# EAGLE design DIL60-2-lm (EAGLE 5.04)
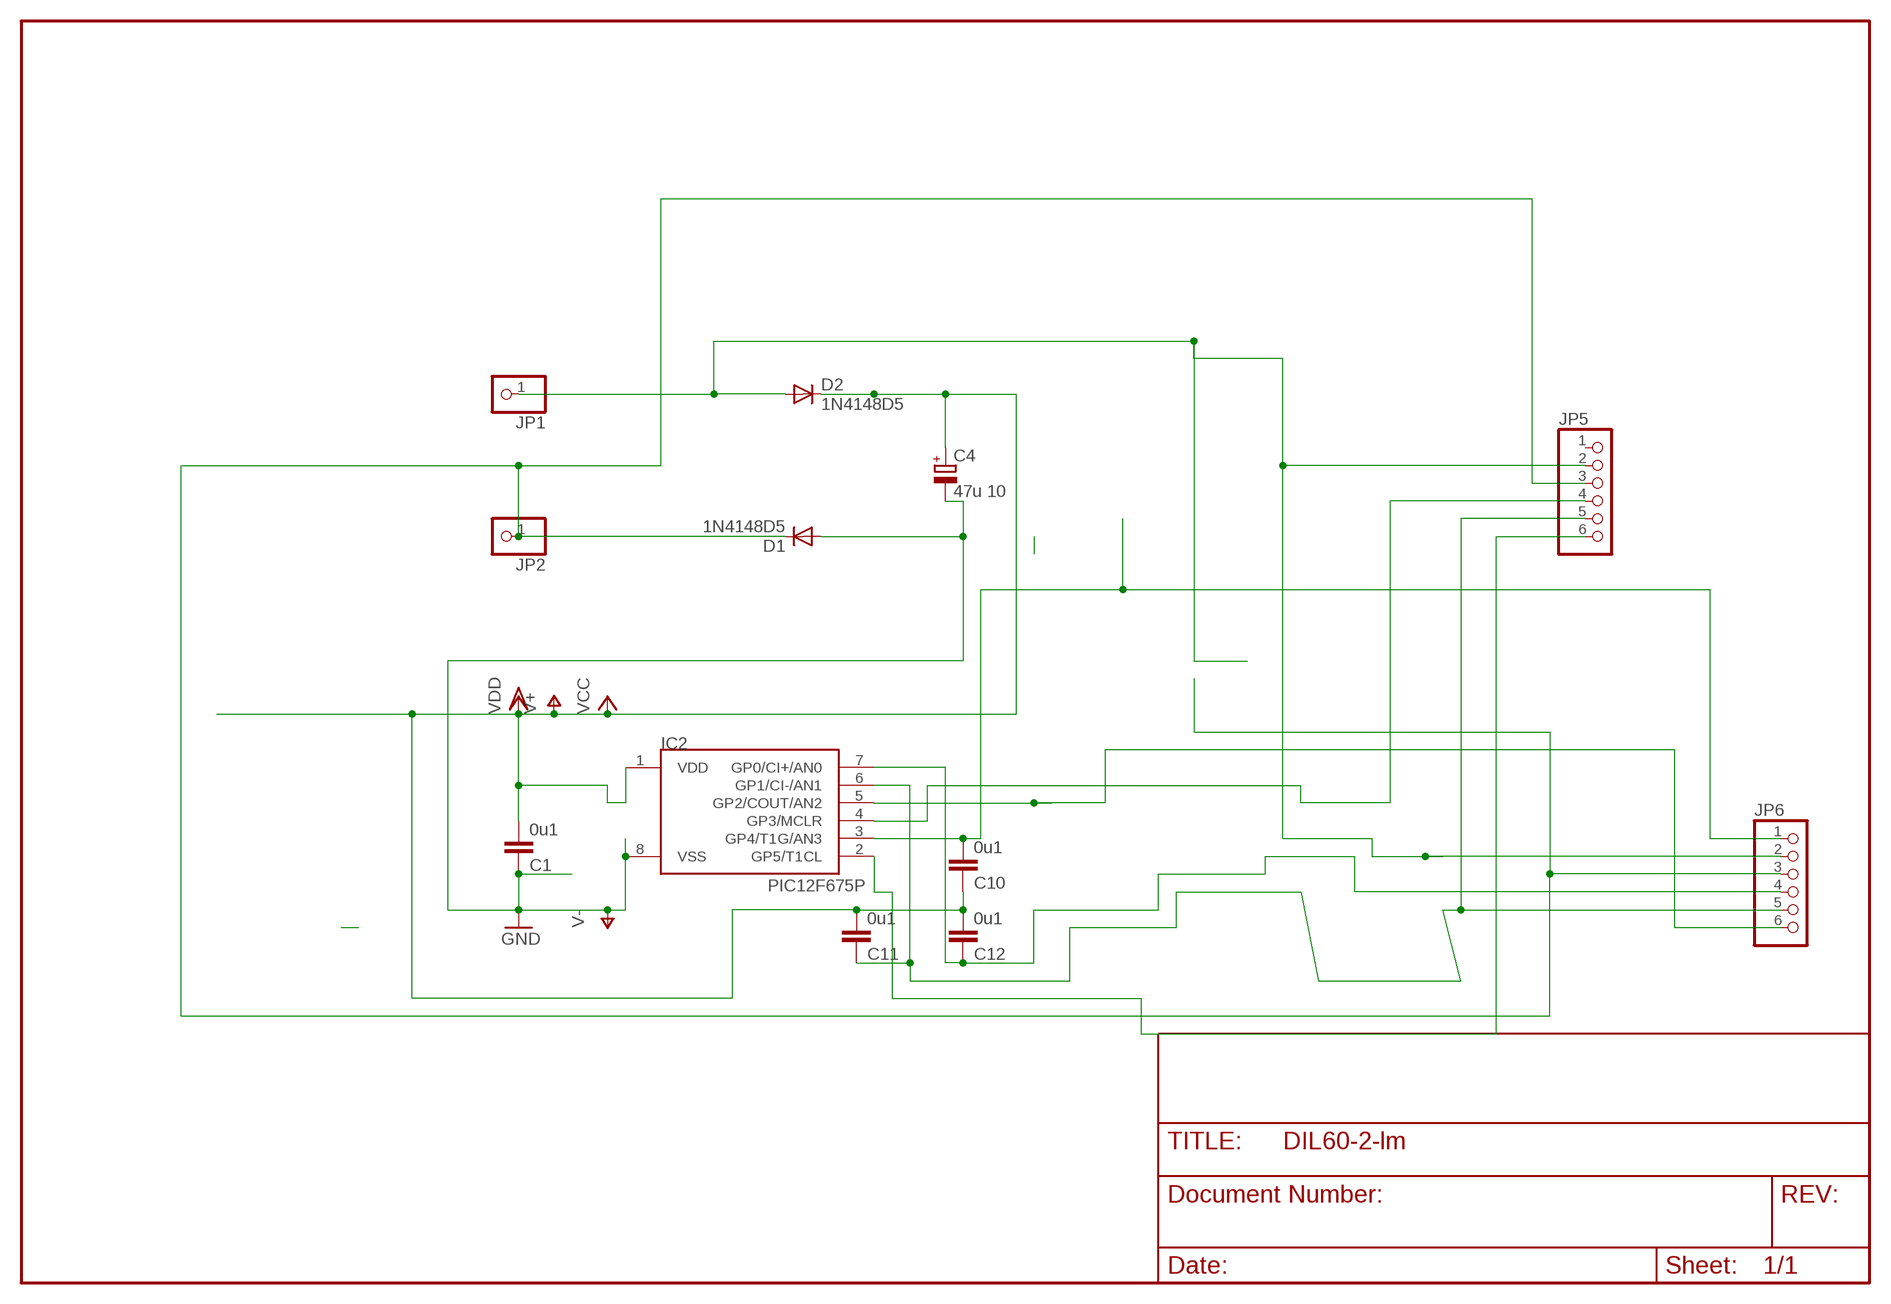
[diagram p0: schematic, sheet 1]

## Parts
C1  0u1  C-EUC1206  [C1206]
C4  47u 10  CPOL-EUE2.5-6  [E2,5-6]
C10  0u1  C-EUC1206  [C1206]
C11  0u1  C-EUC1206  [C1206]
C12  0u1  C-EUC1206  [C1206]
D1  1N4148D5  [D-5]
D2  1N4148D5  [D-5]
IC2  PIC12F675P  [DIL8]
JP1  PINHD-1X1  [1X01]
JP2  PINHD-1X1  [1X01]
JP5  PINHD-1X6  [1X06]
JP6  PINHD-1X6  [1X06]

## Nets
GND: C1.1 C4.- D1.A IC2.8(VSS) ; supply symbol labelled V-
N$2: IC2.5(GP2/COUT/AN2) JP6.6
N$3: IC2.4(GP3/MCLR) JP5.4
N$4: C10.2 IC2.3(GP4/T1G/AN3) JP6.1
N$7: D1.C JP2.1 JP5.3 JP6.3
N$8: IC2.2(GP5/T1CL) JP5.6
N$13: C12.1 IC2.7(GP0/CI+/AN0) JP6.4
N$15: C11.1 IC2.6(GP1/CI-/AN1) JP5.5 JP6.5
V+: C1.2 C4.+ C10.1 C11.2 C12.2 D2.C IC2.1(VDD) ; supply symbol labelled VDD, VCC
VDD: D2.A JP1.1 JP5.2 JP6.2
Unconnected: JP5.1

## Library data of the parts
C1 C10-C12 = rcl:C-EU: CAPACITOR, European symbol
C4 = rcl:CPOL-EU: POLARIZED CAPACITOR, European symbol
D1 D2 = diode:1N4148: DIODE
IC2 = microchip-3:PIC12F6*: uPC nW 1k Program Flash memory 2x Timer Comparator 10b A/D converter/ 4xIN
JP1 JP2 = pinhead:PINHD-1X1: PIN HEADER
JP5 JP6 = pinhead:PINHD-1X6: PIN HEADER

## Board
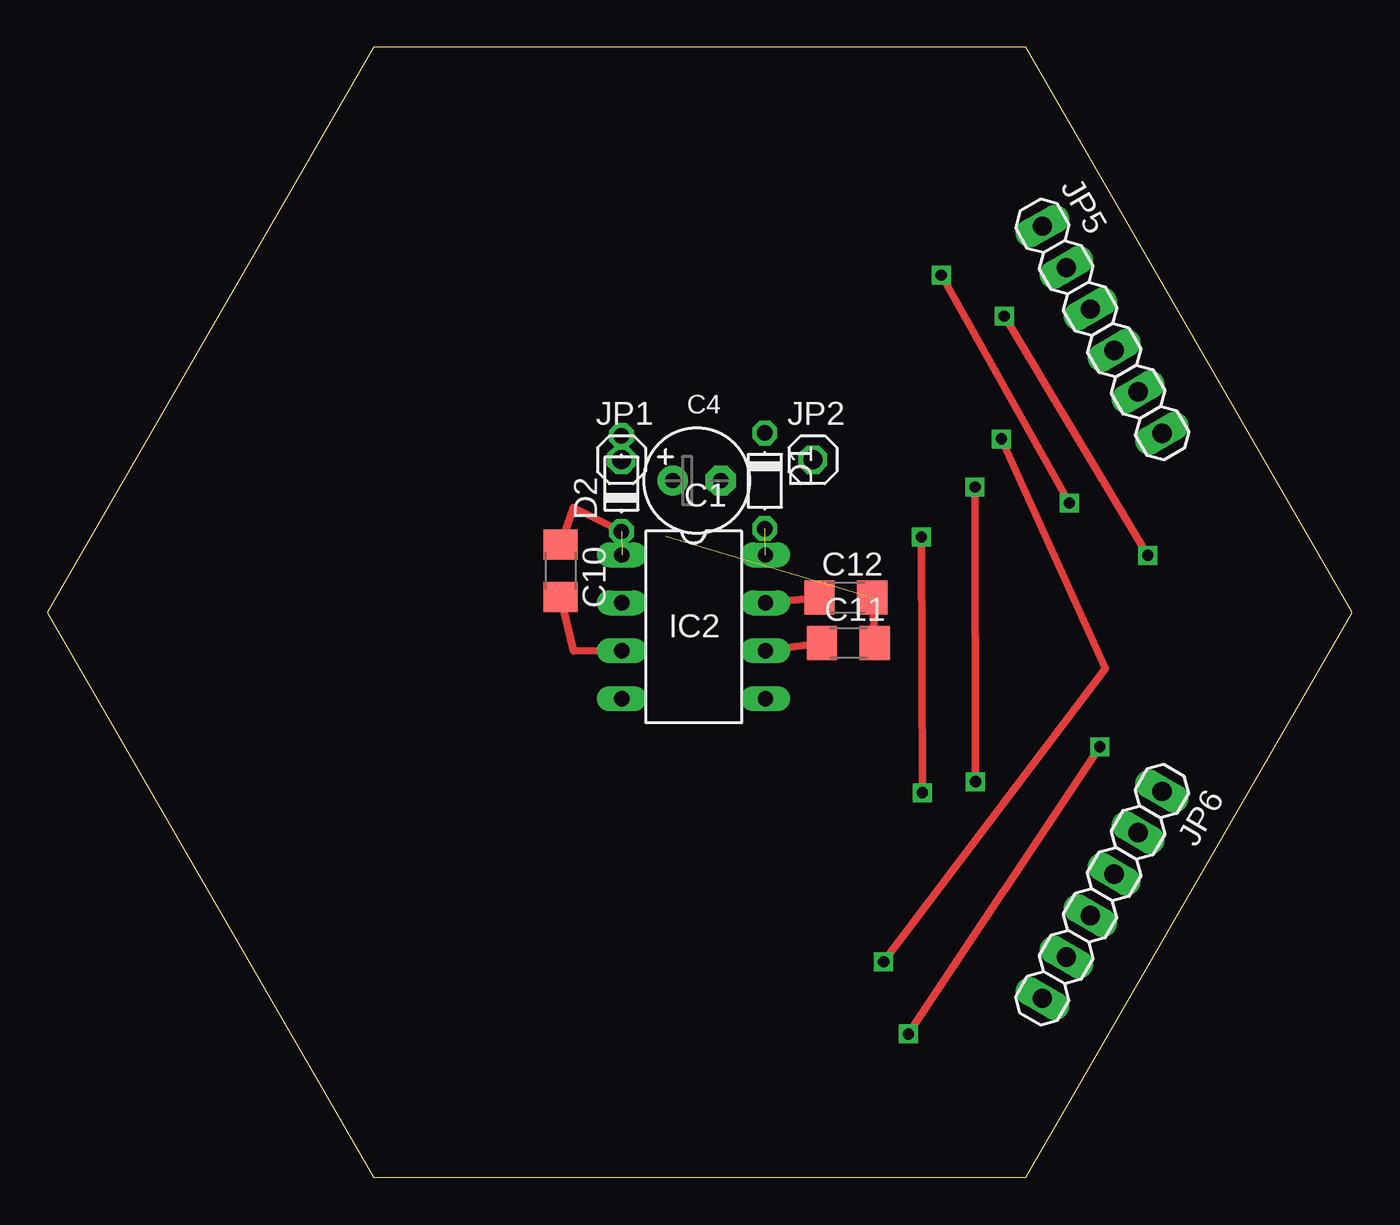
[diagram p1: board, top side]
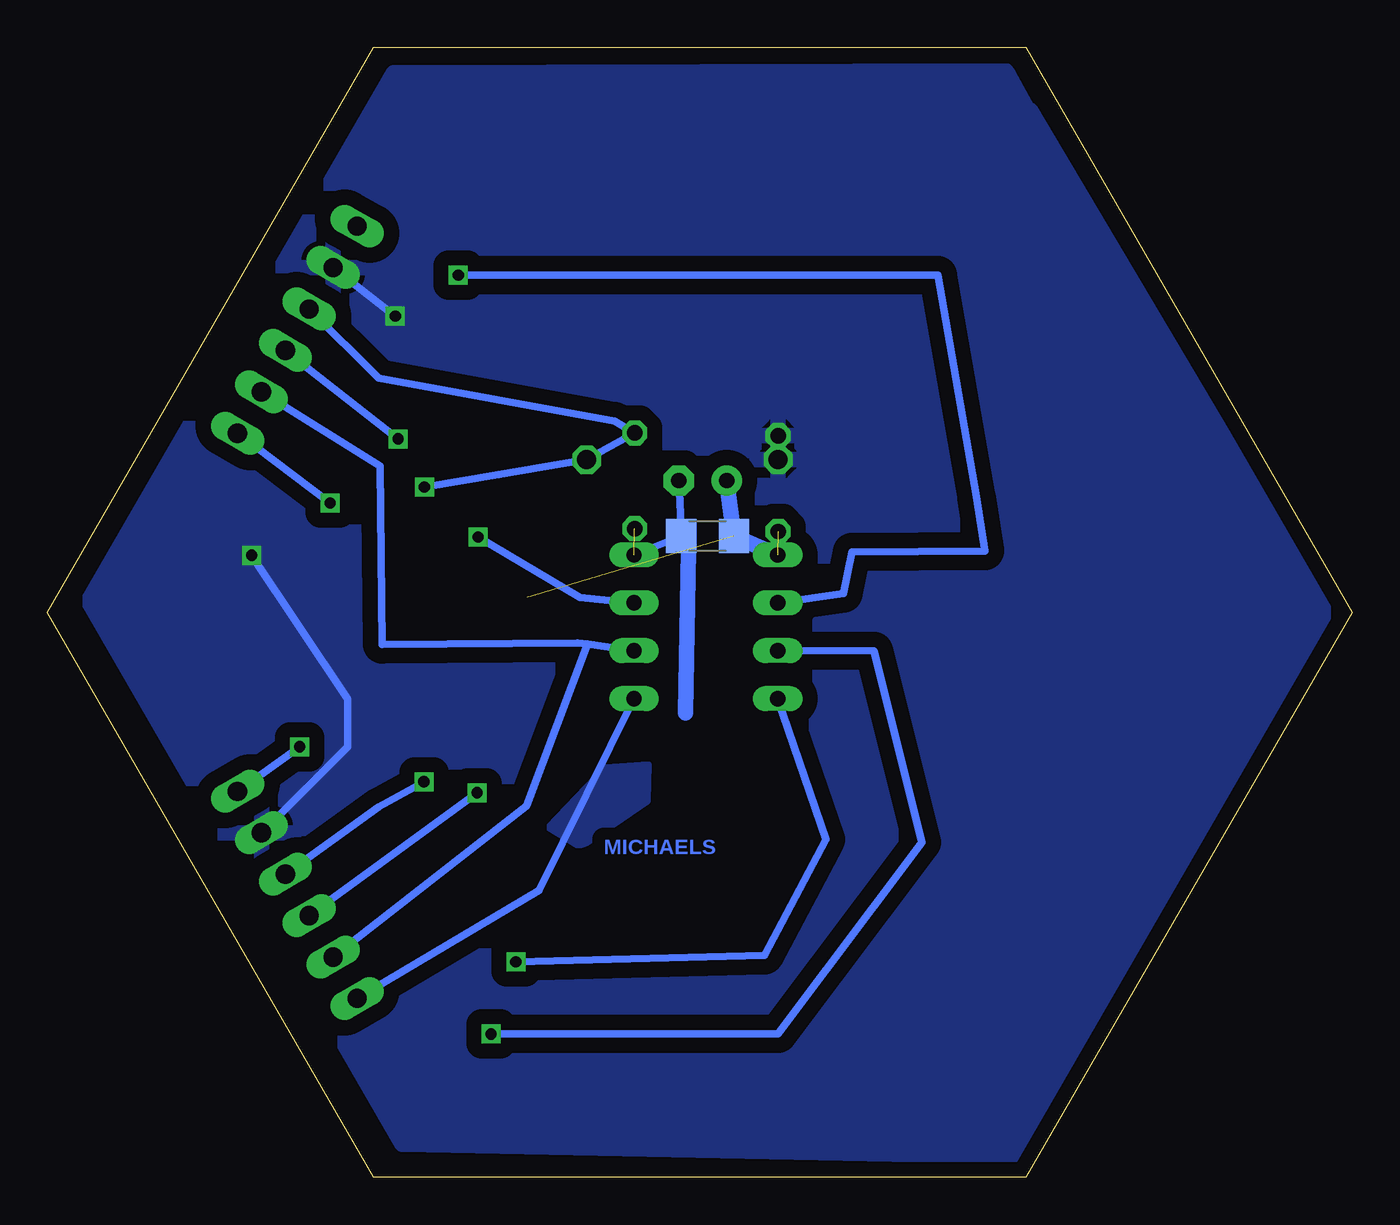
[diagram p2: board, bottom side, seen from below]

Size 69.28 x 60 mm. Coordinates in mm from the lower left corner, seen from the top.
Outline: 17.32,0 51.96,0 69.28,30 51.96,60 17.32,60 0,30 17.32,0
Copper layers (1*16): Top 0.035mm / dielectric 1.5mm / Bottom 0.035mm
Design rules "default *": minimum track width 10mil, minimum drill 24mil, track to track 8mil, track to pad 8mil, pad to pad 8mil, via to via 8mil, smd to smd 8mil, copper to edge 10mil, drill to drill 8mil, minimum pad ring 10mil, minimum via ring 8mil, stop-mask expansion 4mil, vias tented up to drill 0mil, thermal gap 10mil

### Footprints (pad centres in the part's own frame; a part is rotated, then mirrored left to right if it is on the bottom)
C1206 = smd 1.6 x 1.8: 1 -1.4,0; 2 1.4,0
E2,5-6 = drill 0.813 pad 1.6 round: + -1.27,0 | drill 0.813 pad 1.6 octagon: - 1.27,0
D-5 = drill 0.813 octagon: A 2.54,0; C -2.54,0
DIL8 = drill 0.813 long: 1 -3.81,-3.81; 2 -1.27,-3.81; 3 1.27,-3.81; 4 3.81,-3.81; 5 3.81,3.81; 6 1.27,3.81; 7 -1.27,3.81; 8 -3.81,3.81
1X01 = drill 1.016 octagon: 1 0,0
1X06 = drill 1.016 long: 1 -6.35,0; 2 -3.81,0; 3 -1.27,0; 4 1.27,0; 5 3.81,0; 6 6.35,0

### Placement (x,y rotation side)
C1  34.22,34.05 0 bottom
C4  34.48,36.99 0 top
C10  27.25,32.2 270 top
C11  42.53,28.38 0 top
C12  42.39,30.78 0 top
D1  38.09,36.98 270 top
D2  30.48,36.83 90 top
IC2  34.32,29.23 270 top
JP1  30.48,38.1 0 top
JP2  40.64,38.1 0 top
JP5  56,45 300 top
JP6  56,15 240 top

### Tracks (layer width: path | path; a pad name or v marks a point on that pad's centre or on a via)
GND  (1 unrouted)
  Bottom 0.406: C1.1 IC2.8 | 35.25,33.3 C1.1 | C1.1 C4.-
  Bottom 0.813: 35.4,24.65 35.25,33.3
N$2
  Bottom 0.406: JP6.6 43.18,15.24 IC2.5
  pour Bottom (isolate 0.61): 40.64,17.78 37.43,19.99 37.38,21.89 39.63,21.74 42.63,18.59 41.08,17.64
N$3  (via drill 0.6)
  Top 0.406: v50.65,39.2 56.18,27.02 v44.4,11.45
  Bottom 0.406: v50.65,39.2 JP5.4 | v44.4,11.45 31.2,11.8 27.95,17.95 IC2.4
N$4  (via drill 0.6)
  Top 0.406: v45.72,7.62 v55.88,22.86 | C10.2 27.94,27.95 IC2.3
  Bottom 0.406: v55.88,22.86 JP6.1 | v45.72,7.62 30.48,7.62 22.86,17.78 25.4,27.94 IC2.3
N$7  (via drill 0.6)
  Top 0.406: v49.28,21 v49.25,36.65
  Bottom 0.406: JP5.3 51.68,42.44 39.15,40.14 D1.C JP2.1 45.32,37.3 v49.25,36.65 | JP6.3 51.69,19.68 v49.28,21
N$8  (via drill 0.6)
  Top 0.406: v47.46,47.9 v54.26,35.8
  Bottom 0.406: v54.26,35.8 JP5.6 | v47.46,47.9 22,47.9 19.95,36.15 19.5,33.25 26.55,33.2 27,31 IC2.2
N$13  (via drill 0.6)
  Top 0.406: IC2.7 C12.1 | v46.46,20.42 v46.41,34
  Bottom 0.406: JP6.4 v46.46,20.42 | v46.41,34 C12.1 IC2.7
N$15
  Top 0.406: IC2.6 C11.1
  Bottom 0.406: 40.59,28.31 38.79,28.05 IC2.6 | 40.59,28.31 C11.1 51.5,28.3 51.6,37.75 JP5.5 | JP6.5 43.82,19.72 40.59,28.31
V+  (2 unrouted)
  Top 0.406: C11.2 C12.2 | C10.1 27.94,35.56 D2.C
  Bottom 0.813: IC2.1 C1.2 C4.+
VDD  (via drill 0.6)
  Top 0.406: v58.42,33.02 v50.8,45.72
  Bottom 0.406: v50.8,45.72 JP5.2 | v58.42,33.02 53.34,25.4 53.34,22.86 JP6.2
  pour Bottom (isolate 0.813, rank 6): 18.4,58.75 50.9,58.65 67.1,30.6 50.45,1.75 17.95,1.1 1.3,30.05 17.1,56.65 17.1,56.45 18.25,58.55

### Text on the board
Bottom: MICHAELS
